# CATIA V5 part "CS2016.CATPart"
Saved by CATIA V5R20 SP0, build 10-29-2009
Part number: CS2016
Revision: 6
Definition: design
Nomenclature: CS2016
Source: made
Description: NOT SPECIFIED
Bounding box of the stored display mesh (mm): x -15 to 15, y -15 to 15, z -28 to 7.5
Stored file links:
  C:\Users\Raffaele\Desktop\3D X SITO CF\BOLEX\20-TILTED COLUMN SUPPORT\CS2016.CATPart
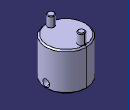
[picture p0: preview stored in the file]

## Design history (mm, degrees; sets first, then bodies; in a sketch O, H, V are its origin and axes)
Body1 "MANIFOLD_SOLID_BREP #691" (main body)
  Solid1: solid without history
